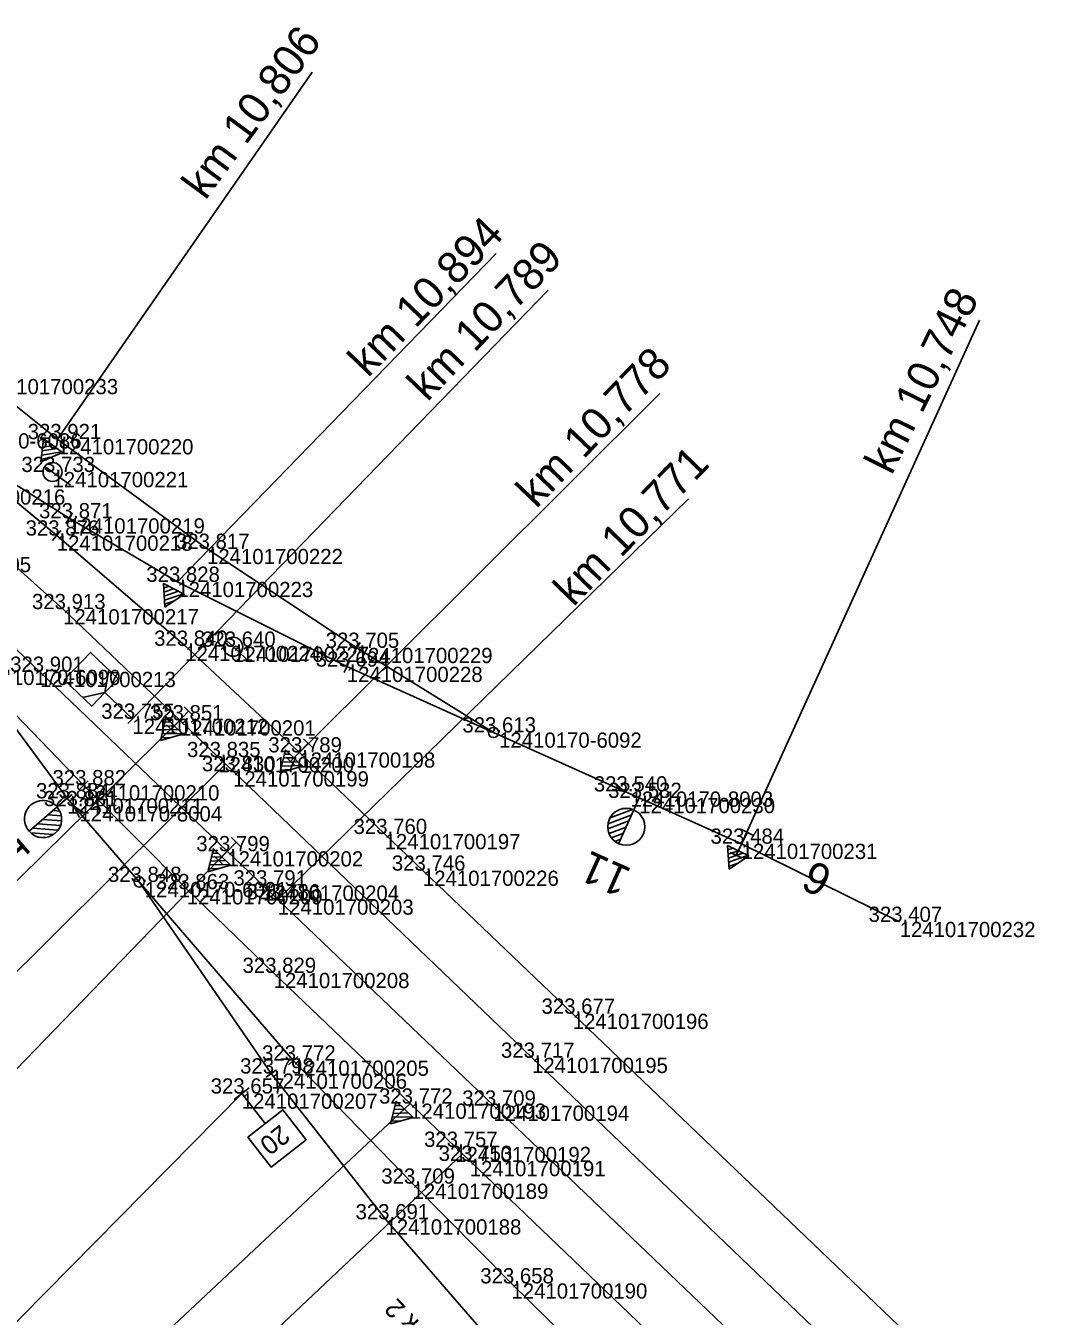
# Model space of a CAD drawing. Extents: x -616949 to -607976, y -1164436 to -1159224.
# Drawn here: x -616499.7 to -616419, y -1159491.5 to -1159389.8 of the extents above; entities that cross this region are included whole.
import ezdxf

# ---------------------------------------------------------------- set-up
doc = ezdxf.new("R2010")
doc.units = 0
for name, color, linetype in [('Vrstva 1', 7, 'Continuous'), ('Vrstva 2', 7, 'Continuous'), ('Vrstva 3', 7, 'Continuous'), ('Vrstva 47', 7, 'Continuous'), ('Vrstva 5', 7, 'Continuous'), ('Vrstva 60', 7, 'Continuous'), ('Vrstva 61', 7, 'Continuous'), ('Vrstva 7', 7, 'Continuous')]:
    doc.layers.add(name, color=color, linetype=linetype)

msp = doc.modelspace()

# ---------------------------------------------------------------- linework, layer by layer
at = {"layer": 'Vrstva 1'}
for points in [[(-616451.35, -1159450.67), (-616452.48, -1159450.16), (-616462.84, -1159445.51), (-616473.62, -1159438.84), (-616485.42, -1159431.04), (-616497.2, -1159422.39), (-616503.14, -1159417.65), (-616511.5, -1159410.5), (-616524.28, -1159398.78), (-616533.45, -1159390.32)], [(-616354.89, -1159571.54), (-616372.69, -1159554.54), (-616388.1, -1159539.8), (-616391.36, -1159536.67), (-616409.17, -1159519.63), (-616429.35, -1159500.31), (-616459.8, -1159471.15), (-616483.37, -1159448.57), (-616484.54, -1159447.45), (-616487.56, -1159444.55), (-616496.77, -1159435.79), (-616507.3, -1159426.35), (-616520.77, -1159414.64), (-616532.81, -1159403.98), (-616540.16, -1159398.34), (-616541.06, -1159397.62)], [(-616358.37, -1159574.75), (-616375.97, -1159557.93), (-616391.41, -1159543.18), (-616394.69, -1159540.05), (-616412.56, -1159522.96), (-616432.68, -1159503.75), (-616462.85, -1159474.92), (-616479.84, -1159458.67), (-616480.99, -1159457.57), (-616483.82, -1159454.87), (-616498.59, -1159440.73), (-616510.42, -1159429.44), (-616522.43, -1159417.95), (-616529.13, -1159411.54), (-616529.76, -1159410.94)], [(-616451.35, -1159450.67), (-616452.48, -1159450.16), (-616462.84, -1159445.51), (-616474.4, -1159440.32), (-616487.76, -1159433.64), (-616496.3, -1159428.63), (-616507, -1159421.93), (-616516.37, -1159415.51), (-616517.32, -1159414.86)], [(-616329.08, -1159589.6), (-616351, -1159568.64), (-616369.15, -1159551.29), (-616384.7, -1159536.43), (-616388.02, -1159533.25), (-616405.95, -1159516.12), (-616426.03, -1159496.92), (-616456.59, -1159467.68), (-616468.4, -1159456.4), (-616471.42, -1159453.51), (-616478.14, -1159447.08), (-616487.14, -1159438.68), (-616497.27, -1159429.99), (-616507, -1159421.93), (-616516.37, -1159415.51), (-616517.32, -1159414.86)], [(-616360.84, -1159578.72), (-616379.28, -1159561.06), (-616394.48, -1159546.5), (-616397.82, -1159543.33), (-616415.45, -1159526.43), (-616435.76, -1159507), (-616464.71, -1159479.28), (-616465.86, -1159478.17), (-616469.41, -1159474.76), (-616480.17, -1159464.46), (-616487.02, -1159457.86), (-616495.15, -1159449.67), (-616503.93, -1159440.57), (-616510.98, -1159431.67), (-616511.76, -1159430.69)], [(-616496.45, -1159450.7), (-616503.93, -1159440.57), (-616510.98, -1159431.67), (-616511.76, -1159430.69)], [(-616458.53, -1159498.36), (-616462.11, -1159494.54), (-616471.35, -1159483.88), (-616480.36, -1159472.39), (-616490.77, -1159457.29), (-616495.92, -1159451.32), (-616496.45, -1159450.7)], [(-616239.15, -1159697.79), (-616239.8, -1159697.28), (-616244.33, -1159693.92), (-616259.78, -1159681.25), (-616268.13, -1159673.95), (-616278.58, -1159664.07), (-616288.41, -1159654.65), (-616299.9, -1159643.65), (-616322.63, -1159621.82), (-616340.65, -1159604.54), (-616363.83, -1159582.4), (-616382.82, -1159564.27), (-616397.71, -1159550.06), (-616401.16, -1159546.79), (-616418.73, -1159530.01), (-616439.27, -1159510.4), (-616452.37, -1159497.82), (-616461.42, -1159488.93), (-616469.22, -1159481.07), (-616478.64, -1159471.37), (-616490.77, -1159457.29), (-616495.92, -1159451.32), (-616496.45, -1159450.7)], [(-616430.82, -1159460.44), (-616443.28, -1159454.28), (-616451.35, -1159450.67)]]:
    msp.add_lwpolyline(points, dxfattribs=at)
at = {"layer": 'Vrstva 2'}
for p, q in [((-616507, -1159421.93), (-616497.27, -1159429.99)), ((-616496.03, -1159428.2), (-616496.56, -1159429.05)), ((-616497.59, -1159430.37), (-616496.95, -1159429.6)), ((-616473.88, -1159439.27), (-616473.35, -1159438.42)), ((-616462.84, -1159445.51), (-616473.62, -1159438.84)), ((-616474.6, -1159440.78), (-616474.19, -1159439.87)), ((-616503.93, -1159440.57), (-616495.15, -1159449.67)), ((-616494.79, -1159449.32), (-616495.51, -1159450.02)), ((-616497.24, -1159451.38), (-616496.45, -1159450.7)), ((-616496.85, -1159451), (-616496.05, -1159450.41)), ((-616451.77, -1159451.61), (-616451.35, -1159450.67)), ((-616497.24, -1159451.38), (-616499.45, -1159453.29)), ((-616496.9, -1159452.09), (-616497.96, -1159452.01)), ((-616497.03, -1159451.7), (-616497.55, -1159451.66)), ((-616451.94, -1159452), (-616453.81, -1159452.71)), ((-616451.88, -1159451.57), (-616453.65, -1159452.25)), ((-616452.97, -1159454.28), (-616451.77, -1159451.61)), ((-616497.17, -1159453.21), (-616499.18, -1159453.06)), ((-616496.97, -1159452.84), (-616498.77, -1159452.71)), ((-616496.89, -1159452.47), (-616498.37, -1159452.36)), ((-616452.16, -1159452.48), (-616453.82, -1159453.11)), ((-616452.38, -1159452.97), (-616453.73, -1159453.48)), ((-616497.54, -1159453.56), (-616499.31, -1159453.43)), ((-616452.6, -1159453.45), (-616453.54, -1159453.81)), ((-616452.81, -1159453.93), (-616453.26, -1159454.1)), ((-616490.77, -1159457.29), (-616480.36, -1159472.39)), ((-616478.26, -1159471.04), (-616479.01, -1159471.7)), ((-616480.77, -1159472.67), (-616479.94, -1159472.1))]:
    msp.add_line(p, q, dxfattribs=at)
for points in [[(-616517.32, -1159414.86), (-616516.37, -1159415.51), (-616507, -1159421.93), (-616496.3, -1159428.63)], [(-616511.76, -1159430.69), (-616510.98, -1159431.67), (-616503.93, -1159440.57), (-616496.45, -1159450.7)], [(-616451.35, -1159450.67), (-616452.48, -1159450.16), (-616462.84, -1159445.51), (-616474.4, -1159440.32)], [(-616453.47, -1159450), (-616452.48, -1159450.16), (-616453.26, -1159449.53)], [(-616496.45, -1159450.7), (-616495.92, -1159451.32), (-616490.77, -1159457.29), (-616478.64, -1159471.37)], [(-616495.09, -1159451.88), (-616495.92, -1159451.32), (-616495.48, -1159452.22)]]:
    msp.add_lwpolyline(points, dxfattribs=at)
for centre, radius in [((-616462.84, -1159445.51), 0.4), ((-616452.37, -1159452.94), 1.46), ((-616490.77, -1159457.29), 0.4)]:
    msp.add_circle(centre, radius, dxfattribs=at)
for centre, start, end in [((-616498.35, -1159452.33), 40.5205, 220.99), ((-616498.34, -1159452.34), 220.7748, 40.7357), ((-616452.37, -1159452.95), 65.8425, 245.8033)]:
    msp.add_arc(centre, 1.46, start, end, dxfattribs=at)
at = {"layer": 'Vrstva 3'}
for p, q in [((-616497.2, -1159422.39), (-616477.12, -1159393.46)), ((-616487.76, -1159433.64), (-616462.63, -1159407.77)), ((-616443.28, -1159454.28), (-616424.52, -1159413.02)), ((-616478.14, -1159447.08), (-616449.72, -1159418.8)), ((-616497.93, -1159422.62), (-616498.35, -1159422.69)), ((-616496.87, -1159423.4), (-616498.45, -1159423.64)), ((-616497.23, -1159423.14), (-616498.42, -1159423.32)), ((-616497.57, -1159422.88), (-616498.39, -1159423.01)), ((-616497.74, -1159423.84), (-616498.48, -1159423.96)), ((-616479.84, -1159458.67), (-616447.46, -1159427.09)), ((-616488.44, -1159433.99), (-616488.84, -1159434.13)), ((-616488.05, -1159434.19), (-616488.82, -1159434.45)), ((-616487.66, -1159434.38), (-616488.81, -1159434.77)), ((-616487.27, -1159434.58), (-616488.78, -1159435.08)), ((-616488.05, -1159435.16), (-616488.76, -1159435.4)), ((-616486.87, -1159443.83), (-616488.25, -1159445.27)), ((-616487.23, -1159443.48), (-616486.51, -1159444.17)), ((-616487.56, -1159444.55), (-616527.67, -1159483.96)), ((-616488, -1159444.99), (-616488.82, -1159445)), ((-616488.31, -1159444.68), (-616488.74, -1159444.69)), ((-616488.62, -1159444.92), (-616487.89, -1159445.62)), ((-616488.29, -1159445.91), (-616489.04, -1159445.93)), ((-616487.37, -1159445.59), (-616488.97, -1159445.62)), ((-616487.69, -1159445.28), (-616488.9, -1159445.31)), ((-616477.81, -1159446.01), (-616477.09, -1159446.71)), ((-616477.45, -1159446.36), (-616478.83, -1159447.81)), ((-616483.96, -1159448.01), (-616523.38, -1159487.17)), ((-616483.37, -1159448.57), (-616484.54, -1159447.45)), ((-616477.94, -1159448.12), (-616479.54, -1159448.16)), ((-616478.26, -1159447.82), (-616479.47, -1159447.85)), ((-616478.57, -1159447.52), (-616479.39, -1159447.54)), ((-616478.89, -1159447.22), (-616479.31, -1159447.23)), ((-616479.19, -1159447.46), (-616478.47, -1159448.15)), ((-616478.86, -1159448.44), (-616479.61, -1159448.47)), ((-616442.39, -1159453.61), (-616443.29, -1159453.16)), ((-616483.13, -1159454.15), (-616484.51, -1159455.6)), ((-616483.49, -1159453.8), (-616482.77, -1159454.49)), ((-616443.72, -1159455.18), (-616442.84, -1159453.38)), ((-616483.82, -1159454.87), (-616519.09, -1159491.31)), ((-616484.25, -1159455.31), (-616485.07, -1159455.33)), ((-616484.57, -1159455.01), (-616484.99, -1159455.02)), ((-616484.87, -1159455.25), (-616484.14, -1159455.94)), ((-616443.95, -1159454.63), (-616444.36, -1159454.77)), ((-616443.56, -1159454.83), (-616444.34, -1159455.09)), ((-616443.18, -1159455.02), (-616444.32, -1159455.41)), ((-616442.78, -1159455.21), (-616444.3, -1159455.73)), ((-616443.27, -1159455.4), (-616444.17, -1159454.96)), ((-616484.54, -1159456.24), (-616485.29, -1159456.26)), ((-616483.62, -1159455.91), (-616485.22, -1159455.95)), ((-616483.94, -1159455.61), (-616485.15, -1159455.64)), ((-616443.56, -1159455.8), (-616444.27, -1159456.04)), ((-616479.84, -1159458.67), (-616480.99, -1159457.57)), ((-616469.41, -1159474.76), (-616509.38, -1159512.21)), ((-616469.54, -1159475.5), (-616470.75, -1159475.53)), ((-616469.85, -1159475.2), (-616470.67, -1159475.22)), ((-616470.16, -1159474.9), (-616470.59, -1159474.91)), ((-616470.14, -1159476.12), (-616470.89, -1159476.15)), ((-616469.22, -1159475.8), (-616470.82, -1159475.84)), ((-616465.29, -1159478.72), (-616505, -1159516.21)), ((-616464.71, -1159479.28), (-616465.86, -1159478.17))]:
    msp.add_line(p, q, dxfattribs=at)
for points in [[(-616498.51, -1159424.18), (-616496.82, -1159423.44), (-616498.31, -1159422.34)], [(-616488.75, -1159435.63), (-616487.21, -1159434.61), (-616488.86, -1159433.78)], [(-616489.1, -1159446.15), (-616487.32, -1159445.63), (-616488.66, -1159444.35)], [(-616479.67, -1159448.69), (-616477.89, -1159448.17), (-616479.23, -1159446.89)], [(-616485.35, -1159456.48), (-616483.57, -1159455.96), (-616484.91, -1159454.68)], [(-616444.26, -1159456.27), (-616442.72, -1159455.24), (-616444.38, -1159454.42)], [(-616470.95, -1159476.36), (-616469.17, -1159475.85), (-616470.51, -1159474.57)]]:
    msp.add_lwpolyline(points, close=True, dxfattribs=at)
at = {"layer": 'Vrstva 47'}
for p, q in [((-616498.2, -1159424.54), (-616496.19, -1159426.02)), ((-616483.91, -1159438.24), (-616482.08, -1159439.94))]:
    msp.add_line(p, q, dxfattribs=at)
for centre in [(-616497.6, -1159424.98), (-616483.36, -1159438.75)]:
    msp.add_circle(centre, 0.75, dxfattribs=at)
at = {"layer": 'Vrstva 5'}
for p, q in [((-616482.09, -1159473.51), (-616483.27, -1159474.43)), ((-616482.68, -1159473.97), (-616514.29, -1159505.99)), ((-616482.68, -1159473.97), (-616480.83, -1159476.33))]:
    msp.add_line(p, q, dxfattribs=at)
msp.add_lwpolyline([(-616482.21, -1159477.41), (-616479.45, -1159475.25), (-616477.6, -1159477.61), (-616480.36, -1159479.77)], close=True, dxfattribs=at)
at = {"layer": 'Vrstva 60'}
for p, q in [((-616497.2, -1159422.39), (-616497.2, -1159422.39)), ((-616497.6, -1159424.98), (-616497.6, -1159424.98)), ((-616496.3, -1159428.63), (-616496.3, -1159428.63)), ((-616497.27, -1159429.99), (-616497.27, -1159429.99)), ((-616485.42, -1159431.04), (-616485.42, -1159431.04)), ((-616487.76, -1159433.64), (-616487.76, -1159433.64)), ((-616496.77, -1159435.79), (-616496.77, -1159435.79)), ((-616487.14, -1159438.68), (-616487.14, -1159438.68)), ((-616483.36, -1159438.75), (-616483.36, -1159438.75)), ((-616473.62, -1159438.84), (-616473.62, -1159438.84)), ((-616498.59, -1159440.73), (-616498.59, -1159440.73)), ((-616474.4, -1159440.32), (-616474.4, -1159440.32)), ((-616491.3, -1159444.43), (-616491.3, -1159444.43)), ((-616487.56, -1159444.55), (-616487.56, -1159444.55)), ((-616462.84, -1159445.51), (-616462.84, -1159445.51)), ((-616478.14, -1159447.08), (-616478.14, -1159447.08)), ((-616484.54, -1159447.45), (-616484.54, -1159447.45)), ((-616483.37, -1159448.57), (-616483.37, -1159448.57)), ((-616495.15, -1159449.67), (-616495.15, -1159449.67)), ((-616452.48, -1159450.16), (-616452.48, -1159450.16)), ((-616496.45, -1159450.7), (-616496.45, -1159450.7)), ((-616451.35, -1159450.67), (-616451.35, -1159450.67)), ((-616495.92, -1159451.32), (-616495.92, -1159451.32)), ((-616471.42, -1159453.51), (-616471.42, -1159453.51)), ((-616443.28, -1159454.28), (-616443.28, -1159454.28)), ((-616483.82, -1159454.87), (-616483.82, -1159454.87)), ((-616490.77, -1159457.29), (-616490.77, -1159457.29)), ((-616468.4, -1159456.4), (-616468.4, -1159456.4)), ((-616487.02, -1159457.86), (-616487.02, -1159457.86)), ((-616480.99, -1159457.57), (-616480.99, -1159457.57)), ((-616479.84, -1159458.67), (-616479.84, -1159458.67)), ((-616430.82, -1159460.44), (-616430.82, -1159460.44)), ((-616480.17, -1159464.46), (-616480.17, -1159464.46)), ((-616456.59, -1159467.68), (-616456.59, -1159467.68)), ((-616478.64, -1159471.37), (-616478.64, -1159471.37)), ((-616459.8, -1159471.15), (-616459.8, -1159471.15)), ((-616480.36, -1159472.39), (-616480.36, -1159472.39)), ((-616482.68, -1159473.97), (-616482.68, -1159473.97)), ((-616469.41, -1159474.76), (-616469.41, -1159474.76)), ((-616462.85, -1159474.92), (-616462.85, -1159474.92)), ((-616465.86, -1159478.17), (-616465.86, -1159478.17)), ((-616464.71, -1159479.28), (-616464.71, -1159479.28)), ((-616469.22, -1159481.07), (-616469.22, -1159481.07)), ((-616471.35, -1159483.88), (-616471.35, -1159483.88)), ((-616461.42, -1159488.93), (-616461.42, -1159488.93))]:
    msp.add_line(p, q, dxfattribs=at)
at = {"layer": 'Vrstva 7'}
for p, q in [((-616491.3, -1159444.43), (-616458.53, -1159410.66)), ((-616493.47, -1159442.35), (-616491.3, -1159444.43)), ((-616491.65, -1159444.79), (-616490.96, -1159444.07))]:
    msp.add_line(p, q, dxfattribs=at)
for points in [[(-616493.47, -1159442.35), (-616492.43, -1159441.27), (-616494.6, -1159439.2), (-616496.67, -1159441.36), (-616494.51, -1159443.44), (-616493.47, -1159442.35)], [(-616495.23, -1159442.74), (-616493.47, -1159442.35), (-616493.16, -1159440.58)]]:
    msp.add_lwpolyline(points, dxfattribs=at)

# ---------------------------------------------------------------- texts
at = {"layer": 'Vrstva 1'}
msp.add_text('6', height=2.5, rotation=153.7115, dxfattribs=at).set_placement((-616435.96, -1159456.34))
at = {"layer": 'Vrstva 2'}
for s, rotation, p in [('12', 130.7553, (-616499.2, -1159455.12)), ('11', 155.8233, (-616451.84, -1159456.3))]:
    msp.add_text(s, height=2.5, rotation=rotation, dxfattribs=at).set_placement(p)
at = {"layer": 'Vrstva 3'}
for s, height, rotation, p in [('km 10,806', 2.5, 53.7158, (-616485.55, -1159403.62)), ('km 10,894', 2.5, 46.0674, (-616472.73, -1159417.6)), ('km 10,748', 2.5, 63.7115, (-616431.45, -1159425.29)), ('km 10,778', 2.5, 46.2635, (-616459.47, -1159427.92)), ('km 10,771', 2.5, 45.9684, (-616456.54, -1159435.67)), ('Vk 2', 1.5, 133.105, (-616467.71, -1159492.94))]:
    msp.add_text(s, height=height, rotation=rotation, dxfattribs=at).set_placement(p)
at = {"layer": 'Vrstva 5'}
msp.add_text('20', height=1.5, rotation=218.0863, dxfattribs=at).set_placement((-616479.65, -1159476.36))
at = {"layer": 'Vrstva 60'}
for s, p in [('124101700233', (-616503.14, -1159418.85)), (' 12410170-6086', (-616507, -1159423.13)), ('124101700220', (-616497.2, -1159423.59)), ('124101700221', (-616497.6, -1159426.18)), ('124101700216', (-616507.3, -1159427.55)), ('124101700219', (-616496.3, -1159429.83)), ('124101700218', (-616497.27, -1159431.19)), (' 12410170-8005', (-616510.98, -1159432.87)), ('124101700222', (-616485.42, -1159432.24)), ('124101700223', (-616487.76, -1159434.84)), ('124101700217', (-616496.77, -1159436.99)), ('124101700224', (-616487.14, -1159439.88)), ('124101700227', (-616483.36, -1159439.95)), ('124101700229', (-616473.62, -1159440.04)), (' 12410170-6090', (-616503.93, -1159441.77)), ('124101700213', (-616498.59, -1159441.93)), ('124101700228', (-616474.4, -1159441.53)), ('124101700212', (-616491.3, -1159445.63)), ('124101700201', (-616487.56, -1159445.75)), (' 12410170-6092', (-616462.84, -1159446.71)), ('124101700198', (-616478.14, -1159448.28)), ('124101700200', (-616484.54, -1159448.65)), ('124101700199', (-616483.37, -1159449.77)), ('124101700210', (-616495.15, -1159450.87)), (' 12410170-8003', (-616452.48, -1159451.36)), ('124101700211', (-616496.45, -1159451.9)), ('124101700230', (-616451.35, -1159451.87)), (' 12410170-8004', (-616495.92, -1159452.52)), ('124101700197', (-616471.42, -1159454.71)), ('124101700231', (-616443.28, -1159455.48)), ('124101700202', (-616483.82, -1159456.07)), (' 12410170-6091', (-616490.77, -1159458.49)), ('124101700226', (-616468.4, -1159457.6)), ('124101700209', (-616487.02, -1159459.06)), ('124101700204', (-616480.99, -1159458.77)), ('124101700203', (-616479.84, -1159459.87)), ('124101700232', (-616430.82, -1159461.64)), ('124101700208', (-616480.17, -1159465.66)), ('124101700196', (-616456.59, -1159468.88)), ('124101700205', (-616478.64, -1159472.57)), ('124101700195', (-616459.8, -1159472.35)), ('124101700206', (-616480.36, -1159473.59)), ('124101700207', (-616482.68, -1159475.17)), ('124101700193', (-616469.41, -1159475.96)), ('124101700194', (-616462.85, -1159476.12)), ('124101700192', (-616465.86, -1159479.37)), ('124101700191', (-616464.71, -1159480.48)), ('124101700189', (-616469.22, -1159482.27)), ('124101700188', (-616471.35, -1159485.08)), ('124101700190', (-616461.42, -1159490.13))]:
    msp.add_text(s, height=1.2, dxfattribs=at).set_placement(p)
at = {"layer": 'Vrstva 61'}
for s, p in [('323.921', (-616499.56, -1159422.39)), ('323.733', (-616500.05, -1159424.98)), ('323.871', (-616498.66, -1159428.63)), ('323.876', (-616499.72, -1159429.99)), ('323.817', (-616487.87, -1159431.04)), ('323.828', (-616490.21, -1159433.64)), ('323.913', (-616499.22, -1159435.79)), ('323.840', (-616489.59, -1159438.68)), ('323.640', (-616485.81, -1159438.75)), ('323.705', (-616476.07, -1159438.84)), ('323.901', (-616500.94, -1159440.73)), ('323.694', (-616476.85, -1159440.32)), ('323.755', (-616493.76, -1159444.43)), ('323.851', (-616489.92, -1159444.55)), ('323.613', (-616465.29, -1159445.51)), ('323.789', (-616480.59, -1159447.08)), ('323.835', (-616487, -1159447.45)), ('323.830', (-616485.82, -1159448.57)), ('323.882', (-616497.6, -1159449.67)), ('323.540', (-616454.93, -1159450.16)), ('323.884', (-616498.9, -1159450.7)), ('323.881', (-616498.28, -1159451.32)), ('323.532', (-616453.8, -1159450.67)), ('323.760', (-616473.87, -1159453.51)), ('323.484', (-616445.73, -1159454.28)), ('323.799', (-616486.27, -1159454.87)), ('323.746', (-616470.85, -1159456.4)), ('323.848', (-616493.23, -1159457.29)), ('323.791', (-616483.34, -1159457.57)), ('323.863', (-616489.47, -1159457.86)), ('323.786', (-616482.3, -1159458.67)), ('323.407', (-616433.27, -1159460.44)), ('323.829', (-616482.62, -1159464.46)), ('323.677', (-616459.05, -1159467.68)), ('323.772', (-616481.08, -1159471.37)), ('323.717', (-616462.25, -1159471.15)), ('323.798', (-616482.81, -1159472.39)), ('323.657', (-616485.13, -1159473.97)), ('323.772', (-616471.86, -1159474.76)), ('323.709', (-616465.3, -1159474.92)), ('323.757', (-616468.31, -1159478.17)), ('323.753', (-616467.16, -1159479.28)), ('323.709', (-616471.68, -1159481.07)), ('323.691', (-616473.71, -1159483.88)), ('323.658', (-616463.88, -1159488.93))]:
    msp.add_text(s, height=1.2, dxfattribs=at).set_placement(p)
at = {"layer": 'Vrstva 7'}
msp.add_text('km 10,789', height=2.5, rotation=46.2484, dxfattribs=at).set_placement((-616468.05, -1159419.51))

doc.saveas('drawing.dxf')
